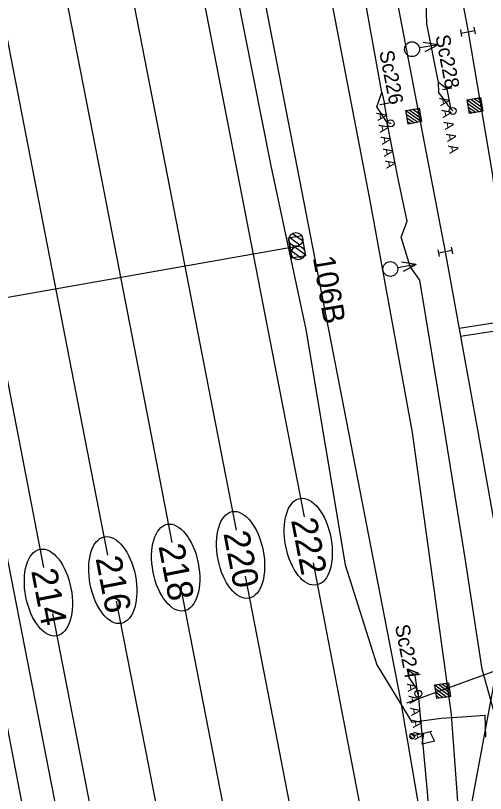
# Model space of a CAD drawing. Extents: x -545846 to -545044, y -1122650 to -1119108.
# Drawn here: x -545472.7 to -545438.5, y -1120309.2 to -1120252.6 of the extents above; entities that cross this region are included whole.
import ezdxf

# ---------------------------------------------------------------- set-up
doc = ezdxf.new("R2010")
doc.units = 0
for name, color, linetype in [('osvětlené plochy-hodnota-obrys', 7, 'Continuous'), ('Vrstva 1', 7, 'Continuous'), ('Vrstva 11 - Trakce', 7, 'Continuous'), ('Vrstva 12 - Trakce zaklady', 7, 'Continuous'), ('Vrstva 2', 7, 'Continuous'), ('Vrstva 26', 7, 'Continuous'), ('Vrstva 27', 7, 'Continuous'), ('Vrstva 28 - zabzar', 7, 'Continuous'), ('Vrstva 3', 7, 'Continuous'), ('Vrstva 3 - Lisy - Pocitaci body', 7, 'Continuous'), ('Vrstva 33', 7, 'Continuous'), ('Vrstva 6 - Navesti', 7, 'Continuous'), ('Vrstva 63', 7, 'Continuous'), ('Vrstva 7', 7, 'Continuous')]:
    doc.layers.add(name, color=color, linetype=linetype)

msp = doc.modelspace()

# ---------------------------------------------------------------- linework, layer by layer
at = {"layer": 'osvětlené plochy-hodnota-obrys'}
for points in [[(-545441.658, -1120319.908), (-545444.67, -1120302.28), (-545584.854, -1119581.025)], [(-545398.15, -1120102.163), (-545405.365, -1120126.289), (-545451.846, -1120376.212), (-545451.085, -1120446.349), (-545447.102, -1120529.01)]]:
    msp.add_lwpolyline(points, dxfattribs=at)
at = {"layer": 'Vrstva 1'}
for points in [[(-545472.265, -1120183.48), (-545467.744, -1120206.583), (-545462.304, -1120234.514), (-545456.879, -1120262.35), (-545453.363, -1120280.44), (-545451.693, -1120289.056)], [(-545477.204, -1120184.536), (-545472.701, -1120207.515), (-545467.253, -1120235.535), (-545461.812, -1120263.44), (-545458.342, -1120281.318), (-545456.649, -1120290.021)], [(-545481.887, -1120185.41), (-545477.398, -1120208.424), (-545471.955, -1120236.309), (-545466.466, -1120264.483), (-545462.985, -1120282.365), (-545461.32, -1120290.93)], [(-545485.879, -1120189.859), (-545482.083, -1120209.385), (-545476.776, -1120236.6), (-545471.193, -1120265.289), (-545467.691, -1120283.289), (-545466.026, -1120291.846)], [(-545490.537, -1120190.87), (-545486.781, -1120210.131), (-545481.46, -1120237.368), (-545475.878, -1120266.029), (-545472.361, -1120284.062), (-545470.669, -1120292.75)], [(-545450.246, -1120199.22), (-545446.762, -1120217.082), (-545443.362, -1120234.651), (-545439.759, -1120253.749), (-545438.016, -1120264.049), (-545436.229, -1120277.953), (-545434.323, -1120299.853)], [(-545454.804, -1120200.615), (-545451.376, -1120218.225), (-545447.958, -1120235.749), (-545441.429, -1120269.771), (-545439.021, -1120283), (-545435.98, -1120300.028)], [(-545459.42, -1120201.744), (-545456.106, -1120218.689), (-545452.573, -1120236.648), (-545446.934, -1120265.899), (-545443.819, -1120282.924), (-545440.985, -1120303.441), (-545439.886, -1120318.431), (-545439.581, -1120327.847), (-545439.227, -1120348.264)], [(-545451.044, -1120292.405), (-545448.723, -1120304.385), (-545444.502, -1120326.373), (-545442.431, -1120338.535), (-545440.887, -1120348.47)], [(-545455.998, -1120293.37), (-545453.664, -1120305.37), (-545450.076, -1120323.917), (-545447.443, -1120343.998), (-545446.977, -1120352.984), (-545446.941, -1120354.265)], [(-545460.669, -1120294.279), (-545458.362, -1120306.144), (-545455.001, -1120323.464), (-545450.984, -1120344.211), (-545449.079, -1120354.472)], [(-545465.375, -1120295.196), (-545463.043, -1120307.184), (-545459.233, -1120326.804), (-545455.702, -1120344.914), (-545452.727, -1120360.241), (-545450.486, -1120372.059)], [(-545470.017, -1120296.1), (-545467.692, -1120308.041), (-545463.828, -1120328.101), (-545460.513, -1120345.373), (-545456.318, -1120367.31), (-545455.226, -1120372.987)], [(-545474.761, -1120297.023), (-545472.421, -1120309.053), (-545468.418, -1120329.586), (-545465.176, -1120346.189), (-545461.046, -1120367.441), (-545459.79, -1120373.88)]]:
    msp.add_lwpolyline(points, dxfattribs=at)
for centre in [(-545451.398, -1120290.864), (-545456.326, -1120291.828), (-545461.054, -1120292.75), (-545465.631, -1120293.657), (-545470.321, -1120294.568)]:
    msp.add_ellipse(centre, major_axis=(0.614, -3.151), ratio=0.521067, dxfattribs=at)
at = {"layer": 'Vrstva 11 - Trakce'}
for p, q in [((-545452.775, -1120268.711), (-545452.002, -1120269.261)), ((-545452.536, -1120268.421), (-545451.808, -1120268.938)), ((-545452.372, -1120269.409), (-545451.643, -1120269.928)), ((-545452.61, -1120269.701), (-545451.839, -1120270.248))]:
    msp.add_line(p, q, dxfattribs=at)
msp.add_lwpolyline([(-545529.615, -1120283.163), (-545514.278, -1120280.398), (-545495.539, -1120277.069), (-545476.856, -1120273.706), (-545452.218, -1120269.354)], dxfattribs=at)
for centre in [(-545452.301, -1120268.861), (-545452.135, -1120269.847)]:
    msp.add_circle(centre, 0.5, dxfattribs=at)
at = {"layer": 'Vrstva 12 - Trakce zaklady'}
for p, q in [((-545452.84, -1120268.736), (-545451.854, -1120268.57)), ((-545451.602, -1120270.065), (-545452.588, -1120270.231))]:
    msp.add_line(p, q, dxfattribs=at)
for points in [[(-545452.588, -1120270.231), (-545452.84, -1120268.736), (-545451.854, -1120268.57), (-545451.602, -1120270.065), (-545452.588, -1120270.231)], [(-545452.84, -1120268.736), (-545452.84, -1120268.736), (-545452.588, -1120270.231), (-545452.588, -1120270.231)], [(-545451.854, -1120268.57), (-545451.854, -1120268.57), (-545451.602, -1120270.065), (-545451.602, -1120270.065)]]:
    msp.add_lwpolyline(points, dxfattribs=at)
at = {"layer": 'Vrstva 26'}
for points in [[(-545472.204, -1120168.419), (-545467.263, -1120195.265), (-545463.403, -1120216.24), (-545462.073, -1120223.095), (-545460.107, -1120233.237), (-545460.477, -1120233.751), (-545456.656, -1120250.779), (-545454.123, -1120263.498), (-545451.565, -1120275.421), (-545448.71, -1120292.559), (-545446.394, -1120299.826), (-545443.86, -1120304), (-545441.73, -1120303.71), (-545440.18, -1120303.61), (-545438.55, -1120303.48), (-545438.492, -1120305.085)], [(-545457.634, -1120373.458), (-545457.64, -1120373.3), (-545460.78, -1120357.25), (-545461.72, -1120355.19), (-545461.53, -1120353.16), (-545465.05, -1120334.52), (-545468.49, -1120316.87), (-545469.02, -1120316.2), (-545469.39, -1120314.66), (-545469.11, -1120313.56), (-545473.02, -1120293.55), (-545476.65, -1120274.97), (-545476.77, -1120274.1), (-545476.856, -1120273.706)]]:
    msp.add_lwpolyline(points, dxfattribs=at)
at = {"layer": 'Vrstva 27'}
for p, q in [((-545440.875, -1120259.535), (-545440.885, -1120259.485)), ((-545445.385, -1120260.445), (-545445.395, -1120260.395)), ((-545443.377, -1120301.945), (-545443.383, -1120301.895))]:
    msp.add_line(p, q, dxfattribs=at)
for centre in [(-545440.88, -1120259.51), (-545445.39, -1120260.42), (-545443.38, -1120301.92)]:
    msp.add_circle(centre, 0.25, dxfattribs=at)
at = {"layer": 'Vrstva 28 - zabzar'}
for p, q in [((-545441.28, -1120257.92), (-545441.92, -1120257.43)), ((-545446.05, -1120258.16), (-545445.85, -1120259)), ((-545445.39, -1120260.42), (-545445.64, -1120260.36)), ((-545443.38, -1120301.92), (-545443.42, -1120301.72))]:
    msp.add_line(p, q, dxfattribs=at)
for points in [[(-545441.92, -1120257.43), (-545442.77, -1120253.18), (-545442.82, -1120251.61), (-545443.2, -1120247.85), (-545444.29, -1120247.75)], [(-545435.765, -1120369.178), (-545435.77, -1120368.34), (-545435.7, -1120360.44), (-545435.61, -1120354.31), (-545434.73, -1120342.05), (-545435.12, -1120337.81), (-545435.22, -1120336.54), (-545436.25, -1120322.58), (-545436.79, -1120315.32), (-545437.22, -1120307.02), (-545437.68, -1120303.89), (-545438.73, -1120300.14), (-545439.97, -1120292.07), (-545441.48, -1120282.7), (-545443.28, -1120271.83), (-545443.98, -1120270.84), (-545444.63, -1120268.7), (-545444.19, -1120267.53), (-545444.84, -1120264.46), (-545445.64, -1120260.36), (-545446.4, -1120259.21), (-545446.05, -1120258.16), (-545447.8, -1120248.31)], [(-545440.88, -1120259.51), (-545441.18, -1120259.16), (-545441.29, -1120258.99), (-545441.9, -1120258.18), (-545441.92, -1120257.43)], [(-545443.6, -1120300.58), (-545444.12, -1120300.25), (-545444.08, -1120300.75), (-545443.42, -1120301.72), (-545442.73, -1120309.07), (-545442.41, -1120313.71), (-545442.27, -1120315.7)]]:
    msp.add_lwpolyline(points, dxfattribs=at)
at = {"layer": 'Vrstva 3'}
for p, q in [((-545440.204, -1120254.087), (-545440.297, -1120253.595)), ((-545439.221, -1120253.903), (-545439.314, -1120253.411)), ((-545440.25, -1120253.841), (-545439.268, -1120253.657)), ((-545441.942, -1120254.699), (-545443.303, -1120254.929)), ((-545441.942, -1120254.699), (-545443.02, -1120254.532)), ((-545441.942, -1120254.699), (-545442.905, -1120255.212)), ((-545440.986, -1120269.43), (-545440.891, -1120269.921)), ((-545441.967, -1120269.621), (-545441.872, -1120270.112)), ((-545440.938, -1120269.676), (-545441.92, -1120269.866)), ((-545443.528, -1120270.677), (-545444.608, -1120270.523)), ((-545443.528, -1120270.677), (-545444.886, -1120270.924)), ((-545443.528, -1120270.677), (-545444.484, -1120271.202))]:
    msp.add_line(p, q, dxfattribs=at)
for centre in [(-545443.838, -1120255.018), (-545445.42, -1120271.019)]:
    msp.add_circle(centre, 0.542, dxfattribs=at)
at = {"layer": 'Vrstva 3 - Lisy - Pocitaci body'}
for p, q in [((-545439.829, -1120258.704), (-545438.677, -1120259.523)), ((-545439.568, -1120258.66), (-545438.721, -1120259.262)), ((-545439.306, -1120258.615), (-545438.765, -1120259)), ((-545439.045, -1120258.571), (-545438.809, -1120258.739)), ((-545439.785, -1120258.965), (-545438.938, -1120259.567)), ((-545439.741, -1120259.227), (-545439.2, -1120259.612)), ((-545444.303, -1120259.487), (-545443.14, -1120260.292)), ((-545444.256, -1120259.748), (-545443.401, -1120260.339)), ((-545444.043, -1120259.44), (-545443.188, -1120260.031)), ((-545443.781, -1120259.392), (-545443.235, -1120259.77)), ((-545443.521, -1120259.345), (-545443.283, -1120259.509)), ((-545439.697, -1120259.488), (-545439.461, -1120259.656)), ((-545444.208, -1120260.009), (-545443.662, -1120260.387)), ((-545444.161, -1120260.27), (-545443.923, -1120260.434)), ((-545441.643, -1120301.209), (-545441.114, -1120301.61)), ((-545441.381, -1120301.173), (-545441.15, -1120301.347)), ((-545442.169, -1120301.282), (-545441.042, -1120302.135)), ((-545442.133, -1120301.544), (-545441.304, -1120302.172)), ((-545441.907, -1120301.245), (-545441.078, -1120301.873)), ((-545442.096, -1120301.807), (-545441.567, -1120302.208)), ((-545442.06, -1120302.07), (-545441.83, -1120302.244))]:
    msp.add_line(p, q, dxfattribs=at)
for points in [[(-545438.843, -1120258.537), (-545438.677, -1120259.523), (-545439.663, -1120259.69), (-545439.829, -1120258.704)], [(-545443.32, -1120259.308), (-545443.14, -1120260.292), (-545444.124, -1120260.471), (-545444.303, -1120259.487)], [(-545441.178, -1120301.145), (-545441.042, -1120302.135), (-545442.032, -1120302.272), (-545442.169, -1120301.282)]]:
    msp.add_lwpolyline(points, close=True, dxfattribs=at)
at = {"layer": 'Vrstva 33'}
for p, q in [((-545444.008, -1120305.021), (-545443.757, -1120305.204)), ((-545443.907, -1120304.851), (-545443.651, -1120305.038)), ((-545442.408, -1120304.675), (-545443.653, -1120304.972)), ((-545443.096, -1120305.595), (-545442.987, -1120304.813)), ((-545442.542, -1120304.707), (-545442.206, -1120305.384)), ((-545442.206, -1120305.384), (-545443.096, -1120305.595))]:
    msp.add_line(p, q, dxfattribs=at)
for major_axis in [(-0.044, -0.195), (-0.044, -0.196)]:
    msp.add_ellipse((-545443.829, -1120305.026), major_axis=major_axis, ratio=0.897978, dxfattribs=at)
at = {"layer": 'Vrstva 6 - Navesti'}
for p, q in [((-545440.936, -1120257.855), (-545441.624, -1120257.985)), ((-545441.023, -1120259.282), (-545441.28, -1120257.92)), ((-545445.506, -1120258.937), (-545446.194, -1120259.063)), ((-545445.602, -1120260.364), (-545445.85, -1120259)), ((-545443.253, -1120300.532), (-545443.947, -1120300.628)), ((-545443.41, -1120301.953), (-545443.6, -1120300.58))]:
    msp.add_line(p, q, dxfattribs=at)
at = {"layer": 'Vrstva 63'}
msp.add_line((-545390.705, -1120283.151), (-545444.248, -1120302.608), dxfattribs=at)
at = {"layer": 'Vrstva 7'}
for p, q in [((-545440.418, -1120275.324), (-545436.642, -1120274.738)), ((-545440.311, -1120275.914), (-545436.566, -1120275.333))]:
    msp.add_line(p, q, dxfattribs=at)

# ---------------------------------------------------------------- texts
at = {"layer": 'Vrstva 11 - Trakce'}
msp.add_text('106B', height=1.6, rotation=279.5679, dxfattribs=at).set_placement((-545451.066, -1120270.174))
at = {"layer": 'Vrstva 2'}
for s, p in [('222', (-545452.655, -1120289.296)), ('220', (-545457.583, -1120290.255)), ('218', (-545462.312, -1120291.179)), ('216', (-545466.892, -1120292.072)), ('214', (-545471.581, -1120292.986))]:
    msp.add_text(s, height=1.875, rotation=280.9117, dxfattribs=at).set_placement(p)
at = {"layer": 'Vrstva 6 - Navesti'}
for s, height, rotation, p in [('Sc228', 1.05, 280.999, (-545442.146, -1120254.065)), ('Sc226', 1.05, 280.9842, (-545446.234, -1120255.206)), ('  A A A A A ', 0.7, 280.6838, (-545441.968, -1120258.05)), ('  A A A A A ', 0.7, 280.3163, (-545446.539, -1120259.125)), ('Sc224', 1.05, 281.0066, (-545445.089, -1120296.985)), ('  A A A A A ', 0.7, 277.8645, (-545444.293, -1120300.676))]:
    msp.add_text(s, height=height, rotation=rotation, dxfattribs=at).set_placement(p)

doc.saveas('drawing.dxf')
